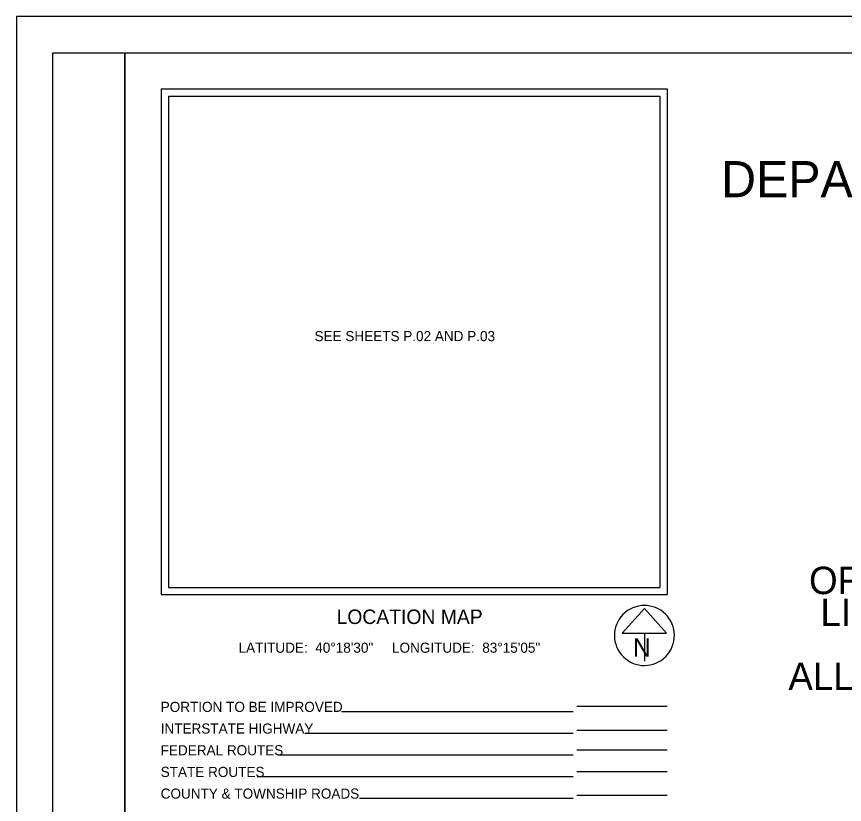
# Model space of a CAD drawing. Extents: x 0 to 34, y 0 to 22.
# Drawn here: x 0 to 11.45, y 11.1 to 22 of the extents above; entities that cross this region are included whole.
import ezdxf

# ---------------------------------------------------------------- set-up
doc = ezdxf.new("R2010")
doc.units = 0
for name, color, linetype in [('SH_Border', 7, 'Continuous'), ('SH_Cut_Line', 7, 'Continuous'), ('SH_Data', 7, 'Continuous'), ('SH_Text', 7, 'Continuous')]:
    doc.layers.add(name, color=color, linetype=linetype)

msp = doc.modelspace()

# ---------------------------------------------------------------- linework, layer by layer
at = {"layer": 'SH_Border'}
for points in [[(0.5, 21.5), (1.5, 21.5), (1.5, 0.5), (0.5, 0.5)], [(1.5, 21.5), (33.5, 21.5), (33.5, 0.5), (1.5, 0.5)]]:
    msp.add_lwpolyline(points, close=True, dxfattribs=at)
at = {"layer": 'SH_Cut_Line'}
msp.add_lwpolyline([(0, 0), (34, 0), (34, 22), (0, 22)], close=True, dxfattribs=at)
at = {"layer": 'SH_Data'}
for p, q in [((2, 21), (9, 21)), ((2, 21), (2, 14)), ((9, 21), (9, 14)), ((2.1, 20.9), (2.1, 14.1)), ((2.1, 20.9), (8.9, 20.9)), ((8.9, 20.9), (8.9, 14.1)), ((2.1, 14.1), (8.9, 14.1)), ((2.1, 14.1), (2.1, 14.1)), ((2, 14), (9, 14)), ((8.685, 13.809), (8.377, 13.468)), ((8.992, 13.468), (8.685, 13.809)), ((8.377, 13.468), (8.992, 13.468)), ((8.685, 13.468), (8.685, 13.081)), ((8.685, 13.435), (8.685, 13.435)), ((8.685, 13.435), (8.685, 13.435)), ((7.7, 12.377), (4.494, 12.377)), ((7.75, 12.455), (9, 12.455)), ((7.7, 12.077), (3.99, 12.077)), ((9, 12.121), (7.75, 12.121)), ((9, 11.849), (7.75, 11.849)), ((7.7, 11.777), (3.619, 11.777)), ((7.7, 11.477), (3.329, 11.477)), ((9, 11.549), (7.75, 11.549)), ((7.7, 11.177), (4.745, 11.177)), ((9, 11.222), (7.75, 11.222))]:
    msp.add_line(p, q, dxfattribs=at)
msp.add_arc((8.685, 13.435), 0.415, 129.7798, 129.7633, dxfattribs=at)

# ---------------------------------------------------------------- texts
msp.add_text('N', height=0.25, dxfattribs=at).set_placement((8.529, 13.144))
at = {"layer": 'SH_Text'}
for s, height, p in [('DEPARTMENT OF TRANSPORTATION', 0.5, (9.747, 19.5)), ('SEE SHEETS P.02 AND P.03', 0.14, (4.122, 17.508)), ('ORANGE, GENOA, BERKSHIRE, KINGSTON, BERLIN,', 0.38, (10.963, 14.007)), ('LIBERTY, DELAWARE, TROY, MARLBORO, SCIOTO,', 0.38, (11.121, 13.565)), ('LOCATION MAP', 0.2, (4.427, 13.594)), ('LATITUDE:  40°18\'30"     LONGITUDE:  83°15\'05"', 0.14, (3.071, 13.196)), ('ALLEN, PARIS, DOVER, MILL CREEK, JEROME, UNION,', 0.38, (10.677, 12.68)), ('PORTION TO BE IMPROVED', 0.14, (1.994, 12.377)), ('INTERSTATE HIGHWAY', 0.14, (1.994, 12.077)), ('FEDERAL ROUTES', 0.14, (1.994, 11.777)), ('STATE ROUTES', 0.14, (1.994, 11.477)), ('COUNTY & TOWNSHIP ROADS', 0.14, (1.994, 11.177))]:
    msp.add_text(s, height=height, dxfattribs=at).set_placement(p)

doc.saveas('drawing.dxf')
